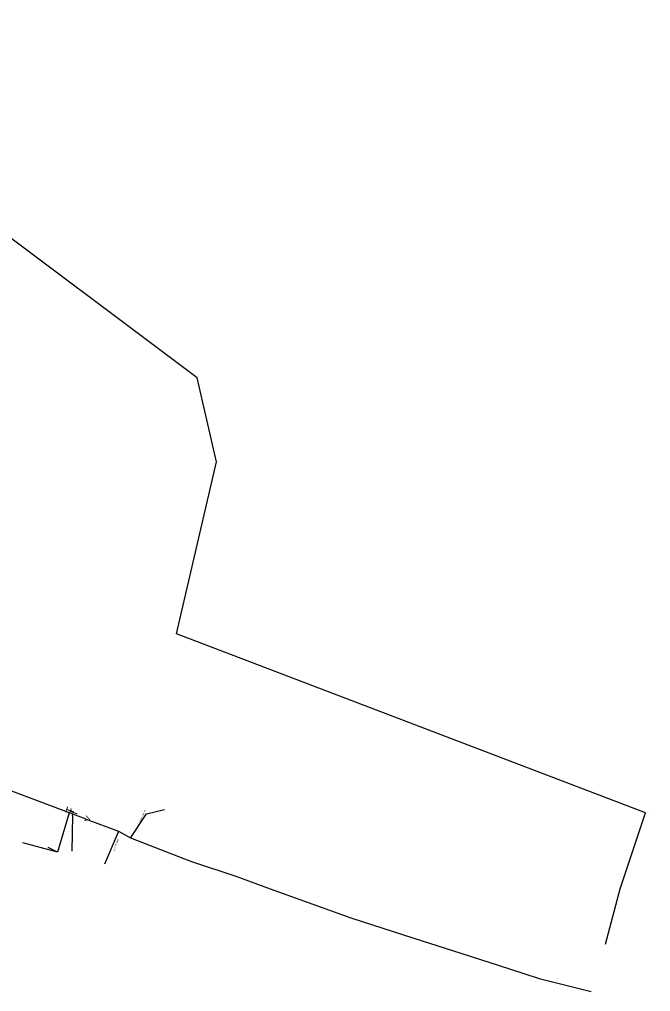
# Model space of a CAD drawing. Extents: x -634006 to -632185, y -1101085 to -1098649.
# Drawn here: x -632422 to -632185.3, y -1099352.1 to -1098987.8 of the extents above; entities that cross this region are included whole.
import ezdxf

# ---------------------------------------------------------------- set-up
doc = ezdxf.new("R2010")
doc.units = 0
for name, color, linetype in [('VP Hydrant', 7, 'Continuous'), ('VP Popis přípojky', 7, 'Continuous'), ('VP Přípojka', 7, 'Continuous'), ('VP Čára nerozlišená', 7, 'Continuous'), ('VP Řad', 7, 'Continuous'), ('VP Šoupě', 7, 'Continuous')]:
    doc.layers.add(name, color=color, linetype=linetype)

msp = doc.modelspace()

# ---------------------------------------------------------------- linework, layer by layer
at = {"layer": 'VP Přípojka'}
for points in [[(-632403.27, -1099285.11), (-632407.63, -1099299.85), (-632420.73, -1099296.35)], [(-632402.04, -1099286.06), (-632402.29, -1099299.49)], [(-632402.04, -1099286.06), (-632401.91, -1099285.62)], [(-632380.29, -1099294.51), (-632380.16, -1099294.3), (-632374.27, -1099285.55), (-632367.57, -1099283.92)], [(-632384.84, -1099292), (-632384.95, -1099292.32), (-632390.07, -1099304.37)], [(-632407.63, -1099299.85), (-632411.18, -1099298.05)]]:
    msp.add_lwpolyline(points, dxfattribs=at)
at = {"layer": 'VP Čára nerozlišená'}
msp.add_line((-632185.28, -1099284.28), (-632185.28, -1099284.28), dxfattribs=at)
at = {"layer": 'VP Řad'}
for points in [[(-632202.21, -1099334.39), (-632196.65, -1099313.61), (-632187.16, -1099285.17), (-632363.05, -1099218.06), (-632348.08, -1099153.53), (-632355.3, -1099122.13), (-632532.17, -1098989.6), (-632533.94, -1098987.76)], [(-632396.88, -1099287.51), (-632459.81, -1099263.88), (-632511.39, -1099245.82), (-632527.44, -1099240.61), (-632542.39, -1099236.04), (-632581.85, -1099223.27), (-632596.16, -1099218.84), (-632622.04, -1099210.36), (-632657.31, -1099199.89), (-632659.55, -1099199.23), (-632678.47, -1099193.61), (-632703.15, -1099186.28), (-632745.01, -1099172.64), (-632755.89, -1099168.68), (-632764.13, -1099166.53), (-632776.15, -1099162.28), (-632787.14, -1099159)], [(-632396.88, -1099287.51), (-632384.84, -1099292), (-632380.29, -1099294.51), (-632360.06, -1099302.35), (-632357, -1099303.52), (-632340.77, -1099308.8), (-632327.88, -1099313.65), (-632297.73, -1099324.47), (-632274.07, -1099332.08), (-632256.47, -1099337.74), (-632238.15, -1099343.61), (-632227.05, -1099347.22), (-632226.6, -1099347.36), (-632207.56, -1099352.1)]]:
    msp.add_lwpolyline(points, dxfattribs=at)

# ---------------------------------------------------------------- texts
at = {"layer": 'VP Hydrant'}
msp.add_text('>', height=3, rotation=339.4207, dxfattribs=at).set_placement((-632398.06, -1099288.3))
at = {"layer": 'VP Popis přípojky'}
for rotation, p in [(67.102, (-632376.51, -1099288.7)), (252.1141, (-632385.2, -1099294.82))]:
    msp.add_text('PRIP DN 32 PE', height=0.5, rotation=rotation, dxfattribs=at).set_placement(p)
at = {"layer": 'VP Šoupě'}
for rotation, p in [(70.47, (-632401.96, -1099285.94)), (69.2759, (-632400.67, -1099286.68))]:
    msp.add_text('T', height=3, rotation=rotation, dxfattribs=at).set_placement(p)

doc.saveas('drawing.dxf')
